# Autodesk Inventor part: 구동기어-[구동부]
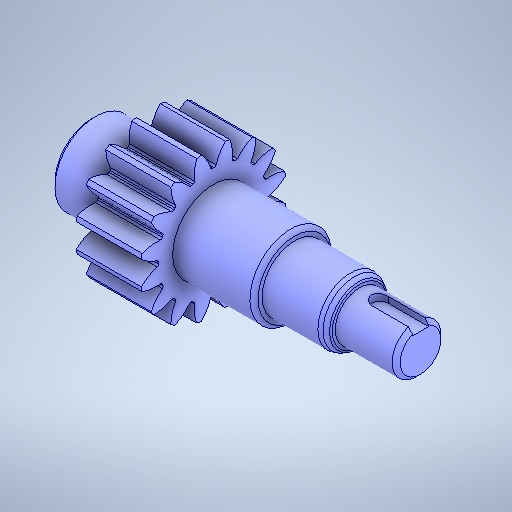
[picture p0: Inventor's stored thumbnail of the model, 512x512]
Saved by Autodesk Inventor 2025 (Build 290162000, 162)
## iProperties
Created: 2026-08
Part Number: 구동기어-[구동부]
Material: 강철, 합금
Document SubType Name: Modeling
Designer: KDI
Density: 7.73 g/cm^3
Appearance: 반연마
Mass: 217.513 g
Surface Area: 80.4282 cm^2
Volume: 28.1387 cm^3
Sending System: Autodesk Inventor 2027
Preprocessor: ST-DEVELOPER v20.1
Author: jhkim
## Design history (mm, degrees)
feature "솔리드1"
node "솔리드2"
